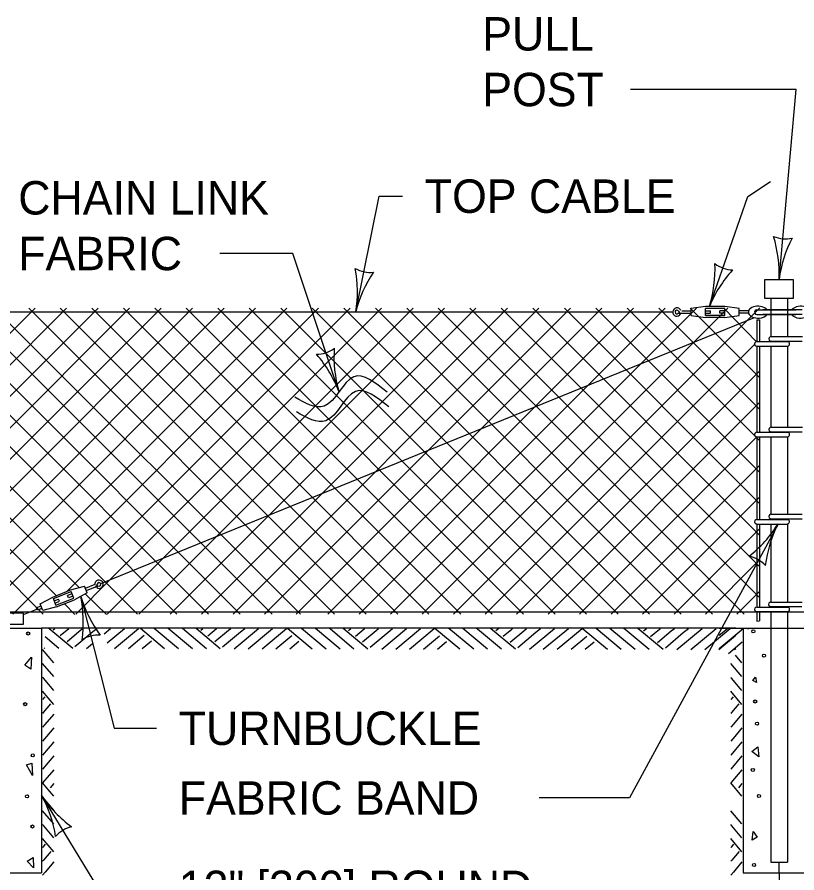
# Model space of a CAD drawing. Extents: x 49973.1 to 50021, y 49987.6 to 50015.4.
# Drawn here: x 50004.311 to 50005.711, y 49991.972 to 49993.509 of the extents above; entities that cross this region are included whole.
import ezdxf

# ---------------------------------------------------------------- set-up
doc = ezdxf.new("R2010")
doc.units = 0
for name, color, linetype in [('Level 1', 7, 'Continuous'), ('Level 2', 7, 'Continuous'), ('Level 3', 7, 'Continuous'), ('Level 6', 7, 'Continuous')]:
    doc.layers.add(name, color=color, linetype=linetype)

msp = doc.modelspace()

# ---------------------------------------------------------------- linework, layer by layer
at = {"layer": 'Level 1'}
for p, q in [((50005.6647, 49993.0039), (50005.6647, 49992.9357)), ((50005.6947, 49993.0039), (50005.6947, 49992.9355)), ((50003.7937, 49992.4372), (50004.343, 49992.9865)), ((50003.8077, 49992.9865), (50004.3573, 49992.4372)), ((50003.8503, 49992.4372), (50004.3996, 49992.9865)), ((50003.8642, 49992.9865), (50004.3808, 49992.4703)), ((50003.9067, 49992.4372), (50004.456, 49992.9865)), ((50003.9215, 49992.9859), (50004.4224, 49992.4847)), ((50003.9633, 49992.4372), (50004.5126, 49992.9865)), ((50003.9776, 49992.9865), (50004.4712, 49992.4926)), ((50004.0199, 49992.4372), (50004.5692, 49992.9865)), ((50004.0489, 49992.9865), (50004.5977, 49992.4372)), ((50004.0765, 49992.4372), (50004.6258, 49992.9865)), ((50004.1056, 49992.9865), (50004.6542, 49992.4372)), ((50004.1331, 49992.4372), (50004.6824, 49992.9865)), ((50004.1622, 49992.9865), (50004.7115, 49992.4372)), ((50004.1897, 49992.4372), (50004.739, 49992.9865)), ((50004.2187, 49992.9864), (50004.7686, 49992.4372)), ((50004.2461, 49992.4372), (50004.7954, 49992.9865)), ((50004.2693, 49992.9865), (50004.8196, 49992.4372)), ((50004.3027, 49992.4372), (50004.852, 49992.9865)), ((50004.3316, 49992.9865), (50004.8806, 49992.4372)), ((50004.3882, 49992.9865), (50004.9375, 49992.4372)), ((50004.4, 49992.478), (50004.9086, 49992.9865)), ((50004.445, 49992.9865), (50004.9943, 49992.4372)), ((50004.4725, 49992.4372), (50005.0218, 49992.9865)), ((50004.4773, 49992.4987), (50004.9652, 49992.9865)), ((50004.5016, 49992.9865), (50005.0503, 49992.4372)), ((50004.5291, 49992.4372), (50005.0784, 49992.9865)), ((50004.5581, 49992.9865), (50005.1074, 49992.4372)), ((50004.5855, 49992.4372), (50005.1348, 49992.9865)), ((50004.6145, 49992.9865), (50005.1638, 49992.4372)), ((50004.6421, 49992.4372), (50005.1914, 49992.9865)), ((50004.6711, 49992.9865), (50005.2204, 49992.4372)), ((50004.6987, 49992.4372), (50005.248, 49992.9865)), ((50004.7277, 49992.9865), (50005.277, 49992.4372)), ((50004.7553, 49992.4372), (50005.3046, 49992.9865)), ((50004.7843, 49992.9865), (50005.3336, 49992.4372)), ((50004.8119, 49992.4372), (50005.3612, 49992.9865)), ((50004.8408, 49992.9865), (50005.3901, 49992.4372)), ((50004.8686, 49992.4372), (50005.4178, 49992.9865)), ((50004.8973, 49992.9865), (50005.4466, 49992.4372)), ((50004.9251, 49992.4372), (50005.4744, 49992.9865)), ((50004.9541, 49992.9865), (50005.5034, 49992.4372)), ((50004.9816, 49992.4372), (50005.5308, 49992.9865)), ((50005.0105, 49992.9865), (50005.5598, 49992.4372)), ((50005.0381, 49992.4372), (50005.5873, 49992.9864)), ((50005.0672, 49992.9865), (50005.6165, 49992.4372)), ((50005.0947, 49992.4372), (50005.6447, 49992.9872)), ((50005.1238, 49992.9865), (50005.6441, 49992.4668)), ((50005.1804, 49992.9865), (50005.6441, 49992.5227)), ((50005.237, 49992.9865), (50005.6441, 49992.5791)), ((50005.2936, 49992.9865), (50005.6441, 49992.6359)), ((50005.35, 49992.9865), (50005.6441, 49992.6923)), ((50005.4066, 49992.9865), (50005.6441, 49992.7491)), ((50005.4632, 49992.9865), (50005.6441, 49992.8053)), ((50005.5198, 49992.9865), (50005.6441, 49992.8621)), ((50005.5474, 49992.9893), (50005.5216, 49992.9861)), ((50005.5216, 49992.9732), (50005.5216, 49992.9861)), ((50005.5817, 49992.9893), (50005.5474, 49992.9893)), ((50005.5817, 49992.9861), (50005.5474, 49992.9861)), ((50005.5474, 49992.9732), (50005.5474, 49992.9861)), ((50005.5802, 49992.9864), (50005.6388, 49992.9261)), ((50005.6074, 49992.9861), (50005.5817, 49992.9893)), ((50005.5817, 49992.9732), (50005.5817, 49992.9861)), ((50005.6074, 49992.9732), (50005.6074, 49992.9861)), ((50003.7525, 49992.9799), (50005.4884, 49992.9799)), ((50005.4986, 49992.978), (50005.5023, 49992.9758)), ((50005.5045, 49992.9818), (50005.5216, 49992.9818)), ((50005.5045, 49992.9775), (50005.5216, 49992.9775)), ((50005.5216, 49992.9732), (50005.5474, 49992.97)), ((50005.5474, 49992.9818), (50005.5559, 49992.9818)), ((50005.5474, 49992.9775), (50005.5559, 49992.9775)), ((50005.5817, 49992.9732), (50005.5474, 49992.9732)), ((50005.5559, 49992.9775), (50005.5559, 49992.9818)), ((50005.5731, 49992.9775), (50005.5731, 49992.9818)), ((50005.5817, 49992.9818), (50005.5731, 49992.9818)), ((50005.5817, 49992.9775), (50005.5731, 49992.9775)), ((50005.5817, 49992.97), (50005.6074, 49992.9732)), ((50005.6244, 49992.9818), (50005.6074, 49992.9818)), ((50005.6244, 49992.9775), (50005.6074, 49992.9775)), ((50005.639, 49992.9833), (50005.7096, 49992.9833)), ((50005.6391, 49992.9752), (50005.7095, 49992.9752)), ((50005.7207, 49992.9833), (50005.6501, 49992.9833)), ((50005.7207, 49992.9752), (50005.6503, 49992.9752)), ((50004.4608, 49992.4919), (50005.6349, 49992.9695)), ((50005.5817, 49992.97), (50005.5474, 49992.97)), ((50005.6391, 49992.9657), (50005.6391, 49992.9264)), ((50005.6391, 49992.9657), (50005.6441, 49992.9657)), ((50005.6441, 49992.9657), (50005.6441, 49992.9264)), ((50005.6392, 49992.9264), (50005.6954, 49992.9264)), ((50005.665, 49992.9355), (50005.7212, 49992.9355)), ((50005.665, 49992.9274), (50005.721, 49992.9274)), ((50005.1511, 49992.4372), (50005.6352, 49992.9213)), ((50005.6391, 49992.9183), (50005.6391, 49992.764)), ((50005.6392, 49992.9183), (50005.6952, 49992.9183)), ((50005.6441, 49992.9183), (50005.6441, 49992.764)), ((50005.6647, 49992.9181), (50005.6647, 49992.7729)), ((50005.6947, 49992.9183), (50005.6947, 49992.773)), ((50005.2077, 49992.4372), (50005.6445, 49992.874)), ((50005.2643, 49992.4372), (50005.6447, 49992.8176)), ((50005.665, 49992.7727), (50005.7212, 49992.7727)), ((50005.3209, 49992.4372), (50005.6394, 49992.7557)), ((50005.6391, 49992.7554), (50005.6391, 49992.6074)), ((50005.6392, 49992.7636), (50005.6954, 49992.7636)), ((50005.6392, 49992.7555), (50005.6952, 49992.7555)), ((50005.6441, 49992.7557), (50005.6441, 49992.6074)), ((50005.6647, 49992.7559), (50005.6647, 49992.6164)), ((50005.665, 49992.7646), (50005.721, 49992.7646)), ((50005.6947, 49992.756), (50005.6947, 49992.6163)), ((50005.3775, 49992.4372), (50005.6444, 49992.7041)), ((50005.4341, 49992.4372), (50005.6446, 49992.6477)), ((50005.639, 49992.607), (50005.6952, 49992.607)), ((50005.6648, 49992.6163), (50005.721, 49992.6163)), ((50005.6648, 49992.6082), (50005.7208, 49992.6082)), ((50005.4907, 49992.4372), (50005.6445, 49992.591)), ((50005.639, 49992.5989), (50005.695, 49992.5989)), ((50005.6391, 49992.5991), (50005.6391, 49992.4497)), ((50005.6441, 49992.5988), (50005.6441, 49992.4497)), ((50005.6647, 49992.5989), (50005.6647, 49992.4587)), ((50005.6947, 49992.5991), (50005.6947, 49992.4586)), ((50005.5471, 49992.4372), (50005.6443, 49992.5344)), ((50004.4159, 49992.4372), (50004.4773, 49992.4987)), ((50004.3746, 49992.4678), (50004.4064, 49992.4805)), ((50004.4064, 49992.4805), (50004.4315, 49992.4871)), ((50004.4363, 49992.4751), (50004.4315, 49992.4871)), ((50004.4504, 49992.49), (50004.4331, 49992.4831)), ((50004.4506, 49992.4855), (50004.4347, 49992.4791)), ((50004.4559, 49992.4881), (50004.4532, 49992.4847)), ((50004.4715, 49992.4928), (50004.527, 49992.437)), ((50004.3519, 49992.4553), (50004.3746, 49992.4678)), ((50004.3758, 49992.4649), (50004.4076, 49992.4775)), ((50004.3805, 49992.4529), (50004.3758, 49992.4649)), ((50004.3774, 49992.4609), (50004.3853, 49992.4641)), ((50004.3805, 49992.4529), (50004.4124, 49992.4656)), ((50004.3869, 49992.4601), (50004.3853, 49992.4641)), ((50004.4092, 49992.4736), (50004.4012, 49992.4704)), ((50004.4028, 49992.4664), (50004.4012, 49992.4704)), ((50004.4108, 49992.4696), (50004.4028, 49992.4664)), ((50004.4124, 49992.4656), (50004.4076, 49992.4775)), ((50004.4363, 49992.4751), (50004.4136, 49992.4626)), ((50004.4332, 49992.4734), (50004.4711, 49992.4365)), ((50005.6037, 49992.4372), (50005.6446, 49992.4781)), ((50004.3534, 49992.4514), (50004.3455, 49992.4482)), ((50004.3471, 49992.4442), (50004.3455, 49992.4482)), ((50004.3566, 49992.4434), (50004.3519, 49992.4553)), ((50004.3817, 49992.4499), (50004.3566, 49992.4434)), ((50004.3789, 49992.4569), (50004.3869, 49992.4601)), ((50004.3817, 49992.4499), (50004.4136, 49992.4626)), ((50004.3955, 49992.4554), (50004.4145, 49992.4365)), ((50005.6393, 49992.4497), (50005.6955, 49992.4497)), ((50005.6644, 49992.4587), (50005.7206, 49992.4587)), ((50005.6644, 49992.4506), (50005.7204, 49992.4506)), ((50003.7561, 49992.441), (50005.6017, 49992.441)), ((50004.3221, 49992.4365), (50004.3463, 49992.4462)), ((50004.355, 49992.4474), (50004.3471, 49992.4442)), ((50005.6017, 49992.4409), (50007.4744, 49992.4409)), ((50005.6391, 49992.4416), (50005.6391, 49992.4242)), ((50005.6393, 49992.4416), (50005.6953, 49992.4416)), ((50005.6441, 49992.4416), (50005.6441, 49992.425)), ((50005.6647, 49992.4416), (50005.6647, 49991.9916)), ((50005.6947, 49992.4416), (50005.6947, 49991.9916)), ((50005.6391, 49992.4242), (50005.6441, 49992.425)), ((50004.2246, 49992.4116), (50004.3546, 49992.4116)), ((50004.3546, 49992.4116), (50004.3546, 49991.9725)), ((50005.6017, 49992.4116), (50004.3546, 49992.4116)), ((50004.4105, 49992.3754), (50004.3676, 49992.4115)), ((50004.3755, 49992.4089), (50004.3786, 49992.4115)), ((50004.3882, 49992.3987), (50004.4036, 49992.4115)), ((50004.4007, 49992.3882), (50004.4253, 49992.4088)), ((50004.4146, 49992.3788), (50004.4469, 49992.4059)), ((50004.4253, 49992.4088), (50004.4286, 49992.4115)), ((50004.4469, 49992.4059), (50004.4537, 49992.4115)), ((50004.467, 49992.4017), (50004.4787, 49992.4115)), ((50004.4726, 49992.3855), (50004.5037, 49992.4115)), ((50004.4855, 49992.3754), (50004.5286, 49992.4115)), ((50004.4855, 49992.3754), (50004.5286, 49992.4115)), ((50004.5756, 49992.3749), (50004.5321, 49992.4115)), ((50004.6006, 49992.3749), (50004.5571, 49992.4115)), ((50004.6256, 49992.3749), (50004.5821, 49992.4115)), ((50004.6076, 49992.411), (50004.6071, 49992.4115)), ((50004.6506, 49992.3749), (50004.6076, 49992.411)), ((50004.6756, 49992.3749), (50004.6321, 49992.4115)), ((50004.6406, 49992.4084), (50004.6443, 49992.4115)), ((50004.6533, 49992.3982), (50004.669, 49992.4113)), ((50004.6658, 49992.3877), (50004.6904, 49992.4083)), ((50004.669, 49992.4113), (50004.6693, 49992.4115)), ((50004.6797, 49992.3783), (50004.712, 49992.4054)), ((50004.6904, 49992.4083), (50004.6943, 49992.4115)), ((50004.7006, 49992.3749), (50004.7444, 49992.4115)), ((50004.712, 49992.4054), (50004.7194, 49992.4115)), ((50004.7256, 49992.3749), (50004.7694, 49992.4115)), ((50004.7506, 49992.3749), (50004.7943, 49992.4115)), ((50004.8407, 49992.3744), (50004.7966, 49992.4115)), ((50004.8657, 49992.3744), (50004.8216, 49992.4115)), ((50004.8907, 49992.3744), (50004.8466, 49992.4115)), ((50004.8727, 49992.4105), (50004.8716, 49992.4115)), ((50004.9157, 49992.3744), (50004.8727, 49992.4105)), ((50004.9407, 49992.3744), (50004.8966, 49992.4115)), ((50004.9057, 49992.4079), (50004.91, 49992.4115)), ((50004.9184, 49992.3977), (50004.9341, 49992.4108)), ((50004.9309, 49992.3872), (50004.9555, 49992.4078)), ((50004.9341, 49992.4108), (50004.935, 49992.4115)), ((50004.9448, 49992.3778), (50004.9771, 49992.4049)), ((50004.9555, 49992.4078), (50004.96, 49992.4115)), ((50004.9657, 49992.3744), (50005.0101, 49992.4115)), ((50004.9771, 49992.4049), (50004.9851, 49992.4115)), ((50004.9907, 49992.3744), (50005.0351, 49992.4115)), ((50005.0157, 49992.3744), (50005.06, 49992.4115)), ((50005.1058, 49992.3739), (50005.0611, 49992.4115)), ((50005.1308, 49992.3739), (50005.0861, 49992.4115)), ((50005.1558, 49992.3739), (50005.1111, 49992.4115)), ((50005.1378, 49992.41), (50005.1361, 49992.4115)), ((50005.1808, 49992.3739), (50005.1378, 49992.41)), ((50005.2058, 49992.3739), (50005.1611, 49992.4115)), ((50005.1708, 49992.4074), (50005.1758, 49992.4116)), ((50005.1835, 49992.3972), (50005.1992, 49992.4103)), ((50005.196, 49992.3867), (50005.2206, 49992.4073)), ((50005.1992, 49992.4103), (50005.2007, 49992.4115)), ((50005.2099, 49992.3773), (50005.2422, 49992.4044)), ((50005.2206, 49992.4073), (50005.2257, 49992.4115)), ((50005.2308, 49992.3739), (50005.2758, 49992.4115)), ((50005.2422, 49992.4044), (50005.2508, 49992.4115)), ((50005.2558, 49992.3739), (50005.3008, 49992.4115)), ((50005.2808, 49992.3739), (50005.3256, 49992.4115)), ((50005.3709, 49992.3734), (50005.3256, 49992.4115)), ((50005.3959, 49992.3734), (50005.3506, 49992.4115)), ((50005.4209, 49992.3734), (50005.3756, 49992.4115)), ((50005.4029, 49992.4095), (50005.4006, 49992.4115)), ((50005.4459, 49992.3734), (50005.4029, 49992.4095)), ((50005.4709, 49992.3734), (50005.4256, 49992.4115)), ((50005.4359, 49992.4069), (50005.4409, 49992.4111)), ((50005.4409, 49992.4111), (50005.4414, 49992.4115)), ((50005.4486, 49992.3967), (50005.4643, 49992.4098)), ((50005.4611, 49992.3862), (50005.4857, 49992.4068)), ((50005.4643, 49992.4098), (50005.4664, 49992.4115)), ((50005.475, 49992.3768), (50005.5073, 49992.4039)), ((50005.4857, 49992.4068), (50005.4914, 49992.4115)), ((50005.4959, 49992.3734), (50005.5414, 49992.4115)), ((50005.5073, 49992.4039), (50005.5165, 49992.4115)), ((50005.5209, 49992.3734), (50005.5664, 49992.4115)), ((50005.5459, 49992.3734), (50005.5913, 49992.4115)), ((50005.5718, 49992.3755), (50005.6147, 49992.4115)), ((50005.6147, 49992.4115), (50005.5718, 49992.4115)), ((50005.5718, 49992.399), (50005.5865, 49992.4114)), ((50005.6147, 49992.4116), (50005.6147, 49991.9725)), ((50005.6147, 49992.4116), (50005.7447, 49992.4116)), ((50005.6224, 49992.4115), (50005.6247, 49992.4115)), ((50004.3855, 49992.3754), (50004.3609, 49992.396)), ((50004.5105, 49992.3754), (50004.5389, 49992.3992)), ((50004.5355, 49992.3754), (50004.5518, 49992.3891)), ((50004.7756, 49992.3749), (50004.804, 49992.3987)), ((50004.8006, 49992.3749), (50004.8169, 49992.3886)), ((50005.0407, 49992.3744), (50005.0691, 49992.3982)), ((50005.0657, 49992.3744), (50005.082, 49992.3881)), ((50005.3058, 49992.3739), (50005.3342, 49992.3977)), ((50005.3308, 49992.3739), (50005.3471, 49992.3876)), ((50005.5709, 49992.3734), (50005.6017, 49992.3991)), ((50005.5884, 49992.3665), (50005.613, 49992.3871)), ((50004.3764, 49992.3498), (50004.3565, 49992.3735)), ((50004.3605, 49992.3754), (50004.3592, 49992.3765)), ((50004.4355, 49992.3754), (50004.4459, 49992.3841)), ((50005.5991, 49992.3735), (50005.6017, 49992.3756)), ((50005.6125, 49992.3498), (50005.601, 49992.3635)), ((50004.3764, 49992.3248), (50004.3565, 49992.3485)), ((50005.6125, 49992.3248), (50005.5926, 49992.3485)), ((50004.358, 49992.3218), (50004.3565, 49992.3235)), ((50004.3764, 49992.2998), (50004.358, 49992.3218)), ((50005.5941, 49992.3218), (50005.5926, 49992.3235)), ((50005.6125, 49992.2998), (50005.5941, 49992.3218)), ((50004.3764, 49992.2748), (50004.3565, 49992.2985)), ((50005.6125, 49992.2748), (50005.5926, 49992.2985)), ((50004.3606, 49992.2888), (50004.3564, 49992.2838)), ((50005.5967, 49992.2888), (50005.5925, 49992.2838)), ((50004.3708, 49992.2761), (50004.3577, 49992.2604)), ((50005.6069, 49992.2761), (50005.5938, 49992.2604)), ((50004.3577, 49992.2604), (50004.3565, 49992.2589)), ((50004.3764, 49992.2577), (50004.3607, 49992.239)), ((50005.5938, 49992.2604), (50005.5926, 49992.2589)), ((50005.6125, 49992.2577), (50005.5968, 49992.239)), ((50004.3607, 49992.239), (50004.3565, 49992.2339)), ((50005.5968, 49992.239), (50005.5926, 49992.2339)), ((50004.3636, 49992.2174), (50004.3565, 49992.2088)), ((50004.3764, 49992.2326), (50004.3636, 49992.2174)), ((50005.5997, 49992.2174), (50005.5926, 49992.2088)), ((50005.6125, 49992.2326), (50005.5997, 49992.2174)), ((50004.3764, 49992.2076), (50004.3565, 49992.1838)), ((50005.6125, 49992.2076), (50005.5926, 49992.1838)), ((50004.3764, 49992.1826), (50004.3565, 49992.1588)), ((50005.6125, 49992.1826), (50005.5926, 49992.1588)), ((50004.3764, 49992.1577), (50004.3565, 49992.134)), ((50005.6125, 49992.1577), (50005.5926, 49992.134)), ((50004.3764, 49992.1103), (50004.3565, 49992.134)), ((50004.3764, 49992.1326), (50004.3703, 49992.1254)), ((50005.6125, 49992.1103), (50005.5926, 49992.134)), ((50005.6125, 49992.1326), (50005.6064, 49992.1254)), ((50004.3764, 49992.0853), (50004.3565, 49992.109)), ((50004.3764, 49992.0603), (50004.3565, 49992.084)), ((50005.6125, 49992.0603), (50005.5926, 49992.084)), ((50004.3585, 49992.0567), (50004.3565, 49992.059)), ((50004.3764, 49992.0353), (50004.3585, 49992.0567)), ((50005.5946, 49992.0567), (50005.5926, 49992.059)), ((50005.6125, 49992.0353), (50005.5946, 49992.0567)), ((50004.3764, 49992.0103), (50004.3565, 49992.034)), ((50005.6125, 49992.0103), (50005.5926, 49992.034)), ((50004.3569, 49992.0187), (50004.3565, 49992.0182)), ((50004.3611, 49992.0237), (50004.3569, 49992.0187)), ((50005.593, 49992.0187), (50005.5926, 49992.0182)), ((50005.5972, 49992.0237), (50005.593, 49992.0187)), ((50004.3713, 49992.011), (50004.3582, 49991.9953)), ((50005.6074, 49992.011), (50005.5943, 49991.9953)), ((50004.3582, 49991.9953), (50004.3565, 49991.9932)), ((50004.3764, 49991.992), (50004.3612, 49991.9739)), ((50005.5943, 49991.9953), (50005.5926, 49991.9932)), ((50005.6125, 49991.992), (50005.5973, 49991.9739)), ((50005.6647, 49991.9916), (50005.6947, 49991.9916)), ((50004.2246, 49991.9725), (50004.3546, 49991.9725)), ((50004.3612, 49991.9739), (50004.3565, 49991.9682)), ((50005.5973, 49991.9739), (50005.5926, 49991.9682)), ((50005.6147, 49991.9725), (50005.7447, 49991.9725))]:
    msp.add_line(p, q, dxfattribs=at)
for points in [[(50005.7048, 49993.0382), (50005.7048, 49993.0039), (50005.6539, 49993.0039), (50005.6539, 49993.0382)], [(50004.2694, 49992.4387), (50004.2694, 49992.419), (50004.3221, 49992.419), (50004.3221, 49992.4387)], [(50004.3244, 49992.3453), (50004.3368, 49992.3597), (50004.3354, 49992.3385)], [(50005.6322, 49992.3179), (50005.637, 49992.3241), (50005.639, 49992.3145)], [(50005.6301, 49992.1903), (50005.6411, 49992.1985), (50005.6432, 49992.1806)], [(50004.3278, 49992.1662), (50004.3374, 49992.1697), (50004.3381, 49992.147)], [(50005.6308, 49992.0311), (50005.6329, 49992.0468), (50005.6397, 49992.0366)], [(50004.3285, 49991.9933), (50004.3395, 49992.0002), (50004.3402, 49991.9817)]]:
    msp.add_lwpolyline(points, close=True, dxfattribs=at)
for centre in [(50004.3306, 49992.4022), (50005.6329, 49992.4063), (50005.6521, 49992.3624), (50005.6363, 49992.2801), (50004.3251, 49992.2753), (50005.6397, 49992.2403), (50004.3388, 49992.1833), (50005.6322, 49992.1572), (50004.3286, 49992.1099), (50005.6432, 49992.1106), (50004.3382, 49992.0557), (50005.6343, 49991.9864)]:
    msp.add_circle(centre, 0.00279, dxfattribs=at)
for centre, radius, start, end in [((50005.4959, 49992.9796), 0.00749, 26.3878, 329.065), ((50005.4959, 49992.9796), 0.00321, 26.3878, 329.7343), ((50005.5045, 49992.9839), 0.00642, 206.3878, 270), ((50005.639, 49992.9793), 0.00405, 89.5405, 270.6652), ((50005.6393, 49992.9224), 0.00405, 87.9212, 274.9002), ((50005.6651, 49992.9315), 0.00405, 87.9212, 274.9002), ((50005.694, 49992.9225), 0.00417, 282.5816, 72.0167), ((50005.6651, 49992.7687), 0.00405, 87.9212, 274.9002), ((50005.6393, 49992.7596), 0.00405, 87.9212, 274.9002), ((50005.694, 49992.7597), 0.00417, 282.5816, 72.0167), ((50005.6391, 49992.603), 0.00405, 87.9212, 274.9002), ((50005.6649, 49992.6123), 0.00405, 87.9212, 274.9002), ((50005.6938, 49992.6031), 0.00417, 282.5816, 72.0167), ((50004.4578, 49992.4907), 0.00749, 232.67, 185.1334), ((50004.4482, 49992.4914), 0.00642, 291.735, 355.3472), ((50004.4578, 49992.4907), 0.00321, 232.0007, 175.3472), ((50005.6391, 49992.4457), 0.00405, 87.9212, 274.9002), ((50005.6645, 49992.4547), 0.00405, 87.9212, 274.9002), ((50005.6941, 49992.4458), 0.00417, 282.5816, 72.0167)]:
    msp.add_arc(centre, radius, start, end, dxfattribs=at)
for centre, major_axis, start_param, end_param in [((50005.6416, 49992.9793), (-0.0175, 0.0001), 3.539885, 7.997344), ((50005.7181, 49992.9793), (0.0175, 0.0001), 4.569027, 9.026485), ((50005.6416, 49992.9793), (-0.0175, 0.0001), 1.714159, 2.761839), ((50005.7181, 49992.9793), (0.0175, 0.0001), 3.521347, 4.569027)]:
    msp.add_ellipse(centre, major_axis=major_axis, ratio=0.610393, start_param=start_param, end_param=end_param, dxfattribs=at)
at = {"layer": 'Level 3'}
for p, q in [((50005.7102, 49993.3792), (50005.4123, 49993.3792)), ((50005.6793, 49993.0382), (50005.7102, 49993.3792)), ((50005.623, 49993.187), (50005.6639, 49993.2142)), ((50004.9191, 49992.9799), (50004.9611, 49993.1877)), ((50004.9611, 49993.1877), (50005.0029, 49993.1877)), ((50005.5541, 49992.9893), (50005.623, 49993.187)), ((50004.8057, 49993.0847), (50004.6747, 49993.0847)), ((50004.8886, 49992.8369), (50004.8057, 49993.0847)), ((50005.6774, 49992.5989), (50005.4106, 49992.1069)), ((50004.4249, 49992.4689), (50004.4848, 49992.2321)), ((50004.4848, 49992.2321), (50004.561, 49992.2321)), ((50005.4106, 49992.1069), (50005.2483, 49992.1069)), ((50005.6797, 49991.9916), (50005.6797, 49991.991)), ((50005.6797, 49991.9725), (50005.6797, 49991.991)), ((50005.6797, 49991.9725), (50005.6797, 49991.6323))]:
    msp.add_line(p, q, dxfattribs=at)
msp.add_lwpolyline([(50004.3546, 49992.1113), (50004.4551, 49991.9464), (50004.561, 49991.9464)], dxfattribs=at)
for centre, radius, start, end in [((50005.6907, 49993.1659), 0.0548, 247.0497, 282.772), ((50005.4465, 49993.0474), 0.233, 357.7382, 16.988), ((50005.8998, 49993.0094), 0.2223, 152.3669, 172.5504), ((50005.3313, 49993.0574), 0.233, 342.9989, 2.2487), ((50005.5976, 49993.1099), 0.0548, 232.3104, 268.0327), ((50004.9452, 49993.1055), 0.0548, 240.4135, 276.1359), ((50004.6889, 49993.016), 0.233, 351.102, 10.3519), ((50005.1347, 49992.9258), 0.2223, 145.7307, 165.9142), ((50005.76, 49992.9053), 0.2223, 137.6276, 157.8111), ((50004.8479, 49992.9585), 0.0548, 270.6438, 306.3662), ((50005.1021, 49992.8988), 0.2223, 175.961, 196.1445), ((50004.6716, 49992.7522), 0.233, 21.3323, 40.5822), ((50005.4883, 49992.716), 0.2223, 308.0447, 328.2282), ((50005.8857, 49992.4947), 0.233, 153.416, 172.6659), ((50005.6144, 49992.4872), 0.0548, 42.7275, 78.4499), ((50004.2073, 49992.4233), 0.2223, 351.6481, 11.8316), ((50004.6477, 49992.5371), 0.233, 197.0194, 216.2693), ((50004.4563, 49992.3446), 0.0548, 86.3309, 122.0533), ((50004.1602, 49992.0034), 0.2223, 8.8475, 29.031), ((50004.5472, 49992.2423), 0.233, 214.2188, 233.4687), ((50004.4213, 49992.0018), 0.0548, 103.5303, 139.2527)]:
    msp.add_arc(centre, radius, start, end, dxfattribs=at)
at = {"layer": 'Level 6'}
for points in [[(50004.9755, 49992.8355), (50004.9153, 49992.8634), (50004.8623, 49992.8106), (50004.8094, 49992.8267)], [(50004.9784, 49992.8091), (50004.9182, 49992.837), (50004.8652, 49992.7842), (50004.8123, 49992.8003)]]:
    msp.add_spline(points, degree=3, dxfattribs=at)

# ---------------------------------------------------------------- texts
at = {"layer": 'Level 2'}
for s, p in [('PULL ', (50005.1461, 49993.4492)), ('POST', (50005.1461, 49993.3492)), ('TOP CABLE', (50005.0429, 49993.1577)), ('CHAIN LINK', (50004.3127, 49993.1547)), ('FABRIC', (50004.3127, 49993.0547)), ('TURNBUCKLE', (50004.601, 49992.2021)), ('FABRIC BAND', (50004.601, 49992.0769)), ('12" [300] ROUND', (50004.601, 49991.9164))]:
    msp.add_text(s, height=0.06, dxfattribs=at).set_placement(p)

doc.saveas('drawing.dxf')
